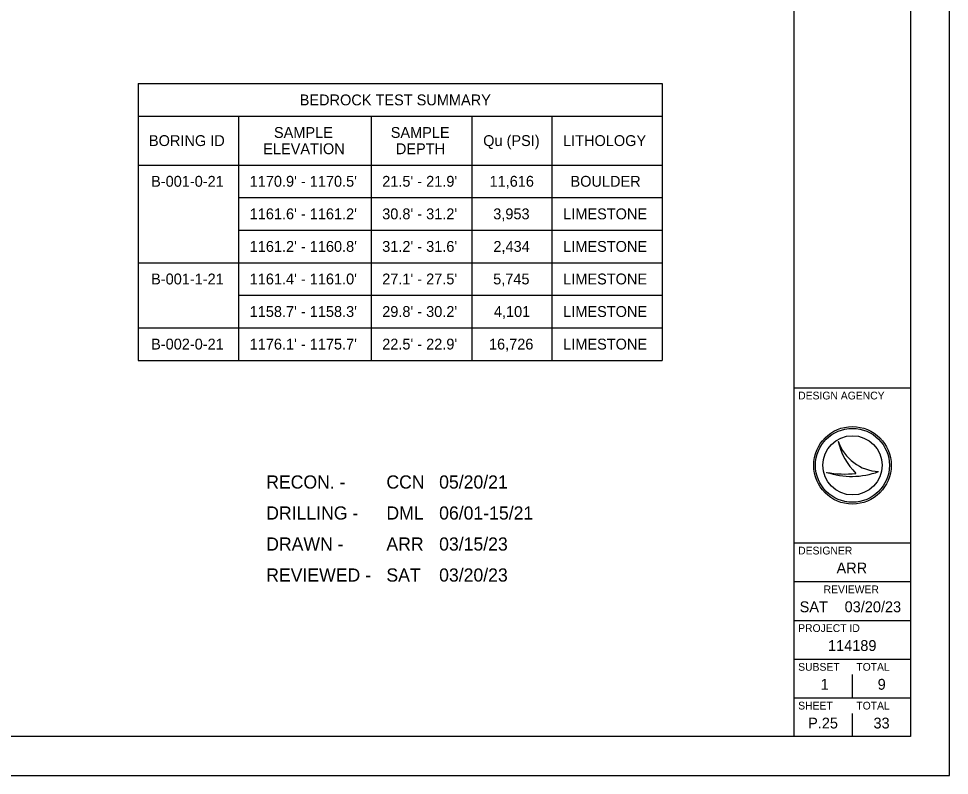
# Model space of a CAD drawing. Extents: x 0 to 34, y 0 to 22.
# Drawn here: x 22 to 34, y 0 to 9.76 of the extents above; entities that cross this region are included whole.
import ezdxf

# ---------------------------------------------------------------- set-up
doc = ezdxf.new("R2010")
doc.units = 0
for name, color, linetype in [('SH_Border', 7, 'Continuous'), ('SH_Cut_Line', 7, 'Continuous'), ('SH_Data', 7, 'Continuous'), ('SH_Text', 7, 'Continuous')]:
    doc.layers.add(name, color=color, linetype=linetype)

msp = doc.modelspace()

# ---------------------------------------------------------------- linework, layer by layer
at = {"layer": 'SH_Border'}
for p, q in [((32, 0.5), (32, 21.5)), ((32, 5), (33.5, 5)), ((32, 3), (33.5, 3)), ((32, 2.5), (33.5, 2.5)), ((32, 2), (33.5, 2)), ((32, 1.5), (33.5, 1.5)), ((32, 1), (33.5, 1))]:
    msp.add_line(p, q, dxfattribs=at)
msp.add_lwpolyline([(1.5, 21.5), (33.5, 21.5), (33.5, 0.5), (1.5, 0.5)], close=True, dxfattribs=at)
at = {"layer": 'SH_Cut_Line'}
msp.add_lwpolyline([(0, 0), (34, 0), (34, 22), (0, 22)], close=True, dxfattribs=at)
at = {"layer": 'SH_Data'}
for p, q in [((23.538, 8.924), (30.296, 8.924)), ((23.538, 8.924), (23.538, 5.354)), ((30.296, 8.924), (30.296, 5.354)), ((23.538, 8.504), (30.296, 8.504)), ((24.837, 5.354), (24.837, 8.504)), ((26.546, 5.354), (26.546, 8.504)), ((27.848, 5.354), (27.848, 8.504)), ((28.878, 5.354), (28.878, 8.504)), ((23.538, 7.874), (30.296, 7.874)), ((24.837, 7.454), (30.296, 7.454)), ((24.837, 7.034), (30.296, 7.034)), ((23.538, 6.614), (30.296, 6.614)), ((24.837, 6.194), (30.296, 6.194)), ((23.538, 5.774), (30.296, 5.774)), ((23.538, 5.354), (30.296, 5.354)), ((32.567, 4.31), (32.567, 4.31)), ((32.75, 4), (32.75, 4)), ((32.417, 3.91), (32.417, 3.91)), ((33.087, 3.919), (33.087, 3.919)), ((32.75, 1), (32.75, 1.3)), ((32.75, 0.5), (32.75, 0.8)), ((32.375, 0.675), (32.375, 0.675))]:
    msp.add_line(p, q, dxfattribs=at)
for radius in [0.5, 0.477, 0.477, 0.382]:
    msp.add_circle((32.75, 4), radius, dxfattribs=at)
for centre, radius, start, end in [((33.116, 4.498), 0.58, 198.9257, 198.9319), ((33.347, 4.47), 0.796, 191.6379, 191.6421), ((33.116, 4.498), 0.58, 198.9319, 267.1657), ((33.347, 4.47), 0.796, 191.6421, 226.0947), ((32.739, 4.87), 1.013, 251.4576, 290.0832), ((32.648, 5.154), 1.266, 259.4964, 259.4995), ((32.739, 4.87), 1.013, 251.4527, 251.4576), ((32.648, 5.154), 1.266, 259.4995, 276.6672)]:
    msp.add_arc(centre, radius, start, end, dxfattribs=at)

# ---------------------------------------------------------------- texts
for s, height, p in [('DESIGN AGENCY', 0.1, (32.05, 4.85)), ('DESIGNER', 0.1, (32.05, 2.85)), ('ARR', 0.14, (32.545, 2.605)), ('REVIEWER', 0.1, (32.378, 2.35)), ('SAT', 0.14, (32.069, 2.105)), ('03/20/23', 0.14, (32.649, 2.105)), ('PROJECT ID', 0.1, (32.05, 1.85)), ('SUBSET', 0.1, (32.05, 1.35)), ('TOTAL', 0.1, (32.8, 1.35)), ('1', 0.14, (32.339, 1.105)), ('9', 0.14, (33.075, 1.105)), ('SHEET', 0.1, (32.05, 0.85)), ('TOTAL', 0.1, (32.8, 0.85)), ('P.25', 0.14, (32.178, 0.605)), ('33', 0.14, (33.021, 0.605))]:
    msp.add_text(s, height=height, dxfattribs=at).set_placement(p)
at = {"layer": 'SH_Text'}
for s, height, p in [('BEDROCK TEST SUMMARY', 0.14, (25.622, 8.644)), ('SAMPLE', 0.14, (25.29, 8.224)), ('SAMPLE', 0.14, (26.796, 8.224)), ('BORING ID', 0.14, (23.678, 8.119)), ('Qu (PSI)', 0.14, (27.988, 8.119)), ('LITHOLOGY', 0.14, (29.018, 8.119)), ('ELEVATION', 0.14, (25.152, 8.014)), ('DEPTH', 0.14, (26.862, 8.014)), ('B-001-0-21', 0.14, (23.706, 7.594)), ("1170.9' - 1170.5'", 0.14, (24.977, 7.594)), ("21.5' - 21.9'", 0.14, (26.686, 7.594)), ('11,616', 0.14, (28.07, 7.594)), ('BOULDER', 0.14, (29.114, 7.594)), ("1161.6' - 1161.2'", 0.14, (24.977, 7.174)), ("30.8' - 31.2'", 0.14, (26.686, 7.174)), ('3,953', 0.14, (28.118, 7.174)), ('LIMESTONE', 0.14, (29.02, 7.174)), ("1161.2' - 1160.8'", 0.14, (24.977, 6.754)), ("31.2' - 31.6'", 0.14, (26.686, 6.754)), ('2,434', 0.14, (28.12, 6.754)), ('LIMESTONE', 0.14, (29.02, 6.754)), ('B-001-1-21', 0.14, (23.706, 6.334)), ("1161.4' - 1161.0'", 0.14, (24.977, 6.334)), ("27.1' - 27.5'", 0.14, (26.686, 6.334)), ('5,745', 0.14, (28.117, 6.334)), ('LIMESTONE', 0.14, (29.02, 6.334)), ("1158.7' - 1158.3'", 0.14, (24.977, 5.914)), ("29.8' - 30.2'", 0.14, (26.686, 5.914)), ('4,101', 0.14, (28.126, 5.914)), ('LIMESTONE', 0.14, (29.02, 5.914)), ('B-002-0-21', 0.14, (23.706, 5.494)), ("1176.1' - 1175.7'", 0.14, (24.977, 5.494)), ("22.5' - 22.9'", 0.14, (26.686, 5.494)), ('16,726', 0.14, (28.063, 5.494)), ('LIMESTONE', 0.14, (29.02, 5.494)), ('RECON. -', 0.17, (25.19, 3.7)), ('CCN', 0.17, (26.74, 3.7)), ('05/20/21', 0.17, (27.42, 3.7)), ('DRILLING -', 0.17, (25.19, 3.3)), ('DML', 0.17, (26.74, 3.3)), ('06/01-15/21', 0.17, (27.42, 3.3)), ('DRAWN -', 0.17, (25.19, 2.9)), ('ARR', 0.17, (26.74, 2.9)), ('03/15/23', 0.17, (27.42, 2.9)), ('REVIEWED -', 0.17, (25.19, 2.5)), ('SAT', 0.17, (26.74, 2.5)), ('03/20/23', 0.17, (27.42, 2.5)), ('114189', 0.14, (32.435, 1.605))]:
    msp.add_text(s, height=height, dxfattribs=at).set_placement(p)

doc.saveas('drawing.dxf')
